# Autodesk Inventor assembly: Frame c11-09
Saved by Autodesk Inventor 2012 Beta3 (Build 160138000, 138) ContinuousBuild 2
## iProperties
Created: 2011-01
Part Number: Frame c11-09
Document SubType Name: Assembly
Designer: Beta-8540w
_FrameDoc: Frame Assembly
_Version: 15.0.0
Author: Beta-8540w
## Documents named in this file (20)
- C:\Inventor 2012 Essentials\Assemblies\Chapter 11\Frame\Frame c11-09.iam
- C:\Inventor 2012 Essentials\Assemblies\Chapter 11\Frame\Skeleton-c11-09.ipt
- C:\Inventor 2012 Essentials\Assemblies\Chapter 11\Frame\ANSI 3x3x3_16 00000043.ipt
- ANSI 3x3x3_16 00000043.ipt
- C:\Inventor 2012 Essentials\Assemblies\Chapter 11\Frame\ANSI 3x3x3_16 00000044.ipt
- ANSI 3x3x3_16 00000044.ipt
- C:\Inventor 2012 Essentials\Assemblies\Chapter 11\Frame\ANSI 3x3x3_16 00000045.ipt
- ANSI 3x3x3_16 00000045.ipt
- C:\Inventor 2012 Essentials\Assemblies\Chapter 11\Frame\ANSI 3x3x3_16 00000046.ipt
- ANSI 3x3x3_16 00000046.ipt
- C:\Inventor 2012 Essentials\Assemblies\Chapter 11\Frame\ANSI 3x3x3_16 00000047.ipt
- ANSI 3x3x3_16 00000047.ipt
- C:\Inventor 2012 Essentials\Assemblies\Chapter 11\Frame\ANSI 3x3x3_16 00000048.ipt
- ANSI 3x3x3_16 00000048.ipt
- C:\Inventor 2012 Essentials\Assemblies\Chapter 11\Frame\ANSI 2 1_4x3_16 00000049.ipt
- ANSI 2 1_4x3_16 00000049.ipt
- C:\Inventor 2012 Essentials\Assemblies\Chapter 11\Frame\ANSI L 1.5 x 1.5 x 3_16 00000050.ipt
- ANSI L 1.5 x 1.5 x 3_16 00000050.ipt
- C:\Inventor 2012 Essentials\Assemblies\Chapter 11\Frame\ANSI L 1.5 x 1.5 x 3_16 00000051.ipt
- ANSI L 1.5 x 1.5 x 3_16 00000051.ipt
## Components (10 placed, 10 different names)
1. Frame Reference Model
2. ANSI 3x3x3_16 00000043:1
3. ANSI 3x3x3_16 00000044:1
4. ANSI 3x3x3_16 00000045:1
5. ANSI 3x3x3_16 00000046:1
6. ANSI 3x3x3_16 00000047:1
7. ANSI 3x3x3_16 00000048:1
8. ANSI 2 1_4x3_16 00000049:1
9. ANSI L 1.5 x 1.5 x 3_16 00000050:1
10. ANSI L 1.5 x 1.5 x 3_16 00000051:1
